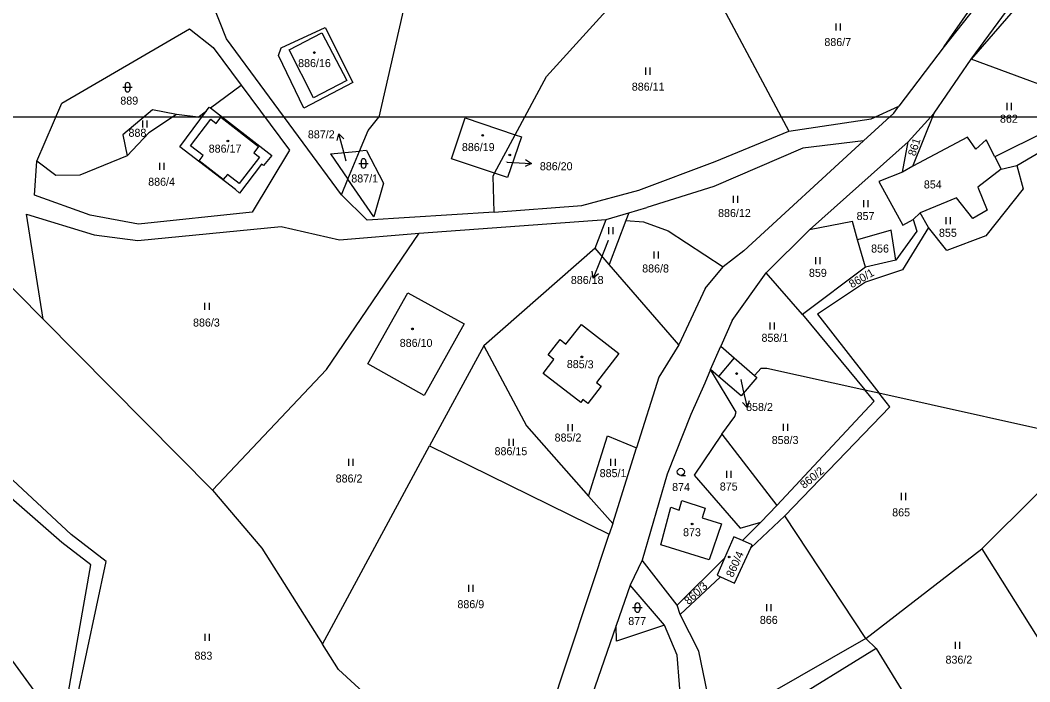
# Model space of a CAD drawing. Extents: x -670359 to -660124, y -978807 to -970072.
# Drawn here: x -669351.9 to -669137.4, y -977619.9 to -977479.4 of the extents above; entities that cross this region are included whole.
import ezdxf

# ---------------------------------------------------------------- set-up
doc = ezdxf.new("R2010")
doc.units = 0
for name, color, linetype in [('Hranice parcel', 7, 'Continuous'), ('ML1000', 7, 'Continuous'), ('Parcelní čísla', 7, 'Continuous'), ('Vnitřní kresba', 7, 'Continuous'), ('Značky budov', 7, 'Continuous'), ('Značky kultur', 7, 'Continuous')]:
    doc.layers.add(name, color=color, linetype=linetype)

msp = doc.modelspace()

# ---------------------------------------------------------------- linework, layer by layer
at = {"layer": 'Hranice parcel'}
for p, q in [((-669296.47, -977485.29), (-669287.14, -977480.93)), ((-669287.14, -977480.93), (-669281.27, -977492.61)), ((-669297.06, -977486.92), (-669296.47, -977485.29)), ((-669291.64, -977498.08), (-669297.06, -977486.92)), ((-669281.27, -977492.61), (-669291.64, -977498.08))]:
    msp.add_line(p, q, dxfattribs=at)
for points in [[(-669108.16, -977439.61), (-669149.88, -977487.66)], [(-669262.21, -977440.81), (-669275.7, -977499.98)], [(-669308.09, -977483.36), (-669317, -977460.78)], [(-669240.07, -977491.32), (-669212, -977460.35)], [(-669155.63, -977485.01), (-669142.12, -977465.6)], [(-669149.88, -977487.66), (-669133.84, -977465.83)], [(-669207.54, -977467.5), (-669188.62, -977502.97)], [(-669141.64, -977467.28), (-669155.63, -977485.01)], [(-669343.06, -977497.02), (-669315.95, -977481.19)], [(-669315.95, -977481.19), (-669310.92, -977485.22)], [(-669310.92, -977485.22), (-669305, -977493.18)], [(-669283.67, -977516.5), (-669308.09, -977483.36)], [(-669155.63, -977485.01), (-669165.21, -977497.66)], [(-669157.76, -977499.16), (-669149.88, -977487.66)], [(-669123.01, -977497.58), (-669149.88, -977487.66)], [(-669246.73, -977503.74), (-669240.07, -977491.32)], [(-669311.5, -977498.03), (-669305, -977493.18)], [(-669305, -977493.18), (-669294.73, -977507.01)], [(-669348.43, -977509.36), (-669343.06, -977497.02)], [(-669312.36, -977498.67), (-669311.75, -977497.84)], [(-669311.75, -977497.84), (-669311.5, -977498.03)], [(-669311.5, -977498.03), (-669298.5, -977508.1)], [(-669171.1, -977500.35), (-669165.21, -977497.66)], [(-669166.33, -977499.14), (-669165.21, -977497.66)], [(-669123.01, -977497.58), (-669144.82, -977508.4)], [(-669323.85, -977498.42), (-669330.14, -977503.73)], [(-669318.73, -977499.43), (-669324.63, -977503.3)], [(-669318.73, -977499.43), (-669323.85, -977498.42)], [(-669314.09, -977499.96), (-669318.73, -977499.43)], [(-669317.98, -977506.3), (-669312.36, -977498.67)], [(-669314.09, -977499.96), (-669312.36, -977498.67)], [(-669278.01, -977502.82), (-669275.7, -977499.98)], [(-669251.12, -977511.91), (-669260.28, -977508.84), (-669257.36, -977500.15)], [(-669257.36, -977500.15), (-669246.73, -977503.74)], [(-669166.33, -977499.14), (-669172.75, -977505.05)], [(-669163.23, -977505.23), (-669157.76, -977499.16)], [(-669162.29, -977510.43), (-669157.76, -977499.16)], [(-669140.19, -977510.25), (-669123.02, -977500.22)], [(-669188.62, -977502.97), (-669171.1, -977500.35)], [(-669330.14, -977503.73), (-669329.24, -977508.2)], [(-669324.63, -977503.3), (-669329.24, -977508.2)], [(-669279.84, -977507.23), (-669278.01, -977502.82)], [(-669251.12, -977511.91), (-669246.73, -977503.74)], [(-669246.73, -977503.74), (-669245.43, -977504.18), (-669248.36, -977512.84), (-669251.12, -977511.91)], [(-669204.3, -977509.42), (-669188.62, -977502.97)], [(-669150.65, -977504.22), (-669162.29, -977510.43)], [(-669148.9, -977506.79), (-669150.65, -977504.22)], [(-669306.22, -977515.38), (-669317.98, -977506.3)], [(-669185.65, -977506.58), (-669204.54, -977514.75)], [(-669198.14, -977528.41), (-669172.75, -977505.05)], [(-669172.75, -977505.05), (-669185.65, -977506.58)], [(-669184.19, -977523.89), (-669163.23, -977505.23)], [(-669164.45, -977511.7), (-669163.23, -977505.23)], [(-669146.65, -977504.79), (-669148.9, -977506.79)], [(-669144.82, -977508.4), (-669146.65, -977504.79)], [(-669329.24, -977508.2), (-669339.29, -977512.34)], [(-669294.73, -977507.01), (-669302.62, -977520.16)], [(-669298.5, -977508.1), (-669300.25, -977510.28)], [(-669285.98, -977507.78), (-669279.84, -977507.23)], [(-669285.98, -977507.78), (-669282.29, -977513.15)], [(-669282.29, -977513.15), (-669279.84, -977507.23)], [(-669278.38, -977507.1), (-669279.84, -977507.23)], [(-669278.38, -977507.1), (-669274.75, -977514.03)], [(-669144.82, -977508.4), (-669143.47, -977511.04)], [(-669348.91, -977516.54), (-669348.43, -977509.36)], [(-669344.33, -977512.37), (-669348.43, -977509.36)], [(-669300.64, -977509.97), (-669305.35, -977516.1)], [(-669300.25, -977510.28), (-669300.64, -977509.97)], [(-669220.45, -977515.51), (-669204.3, -977509.42)], [(-669162.29, -977510.43), (-669164.45, -977511.7)], [(-669143.47, -977511.04), (-669148.45, -977514.87)], [(-669143.47, -977511.04), (-669140.19, -977510.25)], [(-669140.19, -977510.25), (-669138.84, -977515.22)], [(-669339.29, -977512.34), (-669344.33, -977512.37)], [(-669283.67, -977516.5), (-669282.29, -977513.15)], [(-669276.79, -977521.15), (-669282.29, -977513.15)], [(-669251.43, -977512.49), (-669251.12, -977511.91)], [(-669251.24, -977520.17), (-669251.43, -977512.49)], [(-669164.45, -977511.7), (-669169.5, -977513.69)], [(-669274.75, -977514.03), (-669276.79, -977521.15)], [(-669204.54, -977514.75), (-669218.8, -977519.2)], [(-669169.5, -977513.69), (-669164.41, -977522.91)], [(-669148.45, -977514.87), (-669146.46, -977519.76)], [(-669138.84, -977515.22), (-669146.72, -977525.19)], [(-669337.08, -977520.79), (-669348.91, -977516.54)], [(-669305.35, -977516.1), (-669306.22, -977515.38)], [(-669278.22, -977521.9), (-669283.67, -977516.5)], [(-669232.6, -977518.73), (-669220.45, -977515.51)], [(-669153.02, -977517.1), (-669160.72, -977520.28)], [(-669149.51, -977521.51), (-669153.02, -977517.1)], [(-669251.24, -977520.17), (-669232.6, -977518.73)], [(-669222.6, -977520.3), (-669218.8, -977519.2)], [(-669347.06, -977542.92), (-669350.57, -977520.6)], [(-669350.57, -977520.6), (-669336.25, -977524.95)], [(-669326.83, -977522.73), (-669337.08, -977520.79)], [(-669302.62, -977520.16), (-669326.83, -977522.73)], [(-669251.24, -977520.17), (-669278.22, -977521.9)], [(-669267.17, -977524.66), (-669227.45, -977521.71)], [(-669229.76, -977527.85), (-669227.45, -977521.71)], [(-669227.45, -977521.71), (-669222.6, -977520.3)], [(-669222.6, -977520.3), (-669223.23, -977521.96)], [(-669164.41, -977522.91), (-669162.16, -977521.71)], [(-669160.72, -977520.28), (-669162.16, -977521.71)], [(-669162.16, -977521.71), (-669161.45, -977524.19)], [(-669158.97, -977523.4), (-669160.72, -977520.28)], [(-669146.46, -977519.76), (-669149.51, -977521.51)], [(-669326.97, -977526.2), (-669296.46, -977523.22)], [(-669296.46, -977523.22), (-669284.09, -977526.07)], [(-669223.23, -977521.96), (-669226.76, -977531.31)], [(-669223.23, -977521.96), (-669219.49, -977522.19)], [(-669219.49, -977522.19), (-669214.23, -977524.13)], [(-669193.43, -977533.07), (-669184.19, -977523.89)], [(-669175.05, -977522.16), (-669184.19, -977523.89)], [(-669174.03, -977526.08), (-669175.05, -977522.16)], [(-669158.97, -977523.4), (-669164.44, -977532.43)], [(-669155.06, -977528.29), (-669158.97, -977523.4)], [(-669336.25, -977524.95), (-669326.97, -977526.2)], [(-669286.84, -977553.62), (-669267.17, -977524.66)], [(-669284.09, -977526.07), (-669267.17, -977524.66)], [(-669214.23, -977524.13), (-669202.58, -977531.77)], [(-669166.89, -977524.02), (-669174.03, -977526.08)], [(-669165.87, -977530.34), (-669166.89, -977524.02)], [(-669161.45, -977524.19), (-669165.87, -977530.34)], [(-669146.72, -977525.19), (-669155.06, -977528.29)], [(-669363.13, -977526.7), (-669347.06, -977542.92)], [(-669229.76, -977527.85), (-669253.45, -977548.58)], [(-669226.76, -977531.31), (-669229.76, -977527.85)], [(-669172.29, -977531.84), (-669174.03, -977526.08)], [(-669198.14, -977528.41), (-669202.58, -977531.77)], [(-669165.87, -977530.34), (-669172.29, -977531.84)], [(-669211.97, -977548.38), (-669226.76, -977531.31)], [(-669206.41, -977536.39), (-669202.58, -977531.77)], [(-669172.29, -977531.84), (-669185.69, -977541.89)], [(-669164.44, -977532.43), (-669172.3, -977535.05)], [(-669200.67, -977543.21), (-669193.43, -977533.07)], [(-669185.69, -977541.89), (-669193.43, -977533.07)], [(-669206.41, -977536.39), (-669211.97, -977548.38)], [(-669172.3, -977535.05), (-669182.49, -977541.82)], [(-669278.06, -977552.4), (-669269.59, -977537.3)], [(-669269.59, -977537.3), (-669257.59, -977543.88)], [(-669311.1, -977579.22), (-669347.06, -977542.92)], [(-669200.67, -977543.21), (-669203.09, -977548.67)], [(-669185.69, -977541.89), (-669172.45, -977557.92)], [(-669182.49, -977541.82), (-669169.48, -977558.58)], [(-669257.59, -977543.88), (-669266.13, -977559.09)], [(-669236.01, -977548.19), (-669232.68, -977544.03)], [(-669232.68, -977544.03), (-669224.77, -977550.2)], [(-669239.77, -977550.48), (-669237.18, -977547.25)], [(-669237.18, -977547.25), (-669236.01, -977548.19)], [(-669253.45, -977548.58), (-669264.94, -977569.83)], [(-669253.45, -977548.58), (-669244.38, -977565.57)], [(-669211.97, -977548.38), (-669216.24, -977555.25)], [(-669205.27, -977553.6), (-669203.09, -977548.67)], [(-669203.09, -977548.67), (-669200.23, -977551.14)], [(-669240.79, -977554.44), (-669238.57, -977551.46)], [(-669238.57, -977551.46), (-669239.77, -977550.48)], [(-669224.77, -977550.2), (-669229.47, -977556.38)], [(-669200.23, -977551.14), (-669195.88, -977554.9)], [(-669311.1, -977579.22), (-669286.84, -977553.62)], [(-669266.13, -977559.09), (-669278.06, -977552.4)], [(-669205.27, -977553.6), (-669206.44, -977556.51)], [(-669199.77, -977562.65), (-669205.27, -977553.6)], [(-669203.55, -977555.07), (-669205.27, -977553.6)], [(-669195.88, -977554.9), (-669194.52, -977553.32)], [(-669194.52, -977553.32), (-669193.32, -977553.28)], [(-669193.32, -977553.28), (-669172.45, -977557.92)], [(-669232.83, -977560.61), (-669240.79, -977554.44)], [(-669216.24, -977555.25), (-669220.95, -977570.21)], [(-669198.76, -977559.21), (-669203.55, -977555.07)], [(-669195.4, -977555.31), (-669198.76, -977559.21)], [(-669195.88, -977554.9), (-669195.4, -977555.31)], [(-669228.49, -977557.16), (-669231.31, -977560.8)], [(-669229.47, -977556.38), (-669228.49, -977557.16)], [(-669206.44, -977556.51), (-669209.46, -977563.18)], [(-669170.46, -977560.33), (-669172.45, -977557.92)], [(-669172.45, -977557.92), (-669169.48, -977558.58)], [(-669232.36, -977559.99), (-669232.83, -977560.61)], [(-669231.31, -977560.8), (-669232.36, -977559.99)], [(-669191.19, -977582.52), (-669170.46, -977560.33)], [(-669167.18, -977561.54), (-669169.48, -977558.58)], [(-669169.48, -977558.58), (-669124.36, -977568.61)], [(-669167.18, -977561.54), (-669189.44, -977584.68)], [(-669341.12, -977588.67), (-669368.05, -977563.65)], [(-669209.46, -977563.18), (-669214.43, -977575.81)], [(-669202.83, -977567.36), (-669200.09, -977563.61)], [(-669200.09, -977563.61), (-669199.77, -977562.65)], [(-669343.11, -977590.36), (-669370.27, -977566.62)], [(-669244.38, -977565.57), (-669231.17, -977580.52)], [(-669231.17, -977580.52), (-669227.16, -977567.67)], [(-669227.16, -977567.67), (-669220.95, -977570.21)], [(-669202.83, -977567.36), (-669208.7, -977576.07)], [(-669202.83, -977567.36), (-669191.19, -977582.52)], [(-669147.59, -977591.68), (-669124.36, -977568.61)], [(-669287.69, -977611.91), (-669264.94, -977569.83)], [(-669264.94, -977569.83), (-669226.78, -977588.58)], [(-669226.03, -977586.34), (-669220.95, -977570.21)], [(-669214.43, -977575.81), (-669219.81, -977594.12)], [(-669208.7, -977576.07), (-669198.97, -977587.3)], [(-669311.1, -977579.22), (-669300.56, -977591.54)], [(-669226.03, -977586.34), (-669231.17, -977580.52)], [(-669211.93, -977583.5), (-669211.36, -977581.42)], [(-669211.36, -977581.42), (-669206.41, -977583.04)], [(-669215.8, -977590.85), (-669213.69, -977582.85)], [(-669213.69, -977582.85), (-669211.93, -977583.5)], [(-669206.41, -977583.04), (-669207.05, -977585.11)], [(-669194.57, -977586.03), (-669191.19, -977582.52)], [(-669207.05, -977585.11), (-669202.89, -977586.41)], [(-669198.97, -977587.3), (-669194.57, -977586.03)], [(-669194.57, -977586.03), (-669198.48, -977589.92)], [(-669189.44, -977584.68), (-669196.67, -977591.5)], [(-669172.23, -977610.73), (-669189.44, -977584.68)], [(-669226.03, -977586.34), (-669226.78, -977588.58)], [(-669202.89, -977586.41), (-669205.56, -977594)], [(-669336.93, -977595.11), (-669343.11, -977590.36)], [(-669333.65, -977594.37), (-669341.12, -977588.67)], [(-669239.62, -977627.27), (-669226.78, -977588.58)], [(-669200.29, -977589.11), (-669202.28, -977593.69)], [(-669198.48, -977589.92), (-669200.29, -977589.11)], [(-669196.37, -977590.86), (-669198.48, -977589.92)], [(-669300.56, -977591.54), (-669287.69, -977611.91)], [(-669205.56, -977594), (-669215.8, -977590.85)], [(-669200.17, -977599.01), (-669196.67, -977591.5)], [(-669196.67, -977591.5), (-669196.37, -977590.86)], [(-669172.23, -977610.73), (-669147.59, -977591.68)], [(-669147.59, -977591.68), (-669130.3, -977619.14)], [(-669339.81, -977623.26), (-669333.65, -977594.37)], [(-669219.81, -977594.12), (-669222.31, -977599.39)], [(-669212.32, -977603.66), (-669219.81, -977594.12)], [(-669202.28, -977593.69), (-669212.32, -977603.66)], [(-669202.28, -977593.69), (-669203.85, -977597.29)], [(-669347.25, -977624.1), (-669368.28, -977595.3)], [(-669341.89, -977623.27), (-669336.93, -977595.11)], [(-669203.16, -977597.61), (-669211.69, -977605.66)], [(-669203.85, -977597.29), (-669203.16, -977597.61)], [(-669203.16, -977597.61), (-669200.17, -977599.01)], [(-669222.31, -977599.39), (-669225.3, -977607.95)], [(-669215.06, -977607.89), (-669222.31, -977599.39)], [(-669211.69, -977605.66), (-669212.32, -977603.66)], [(-669207.71, -977613.43), (-669211.69, -977605.66)], [(-669225.3, -977607.95), (-669231.13, -977624.73)], [(-669225.24, -977611.31), (-669225.3, -977607.95)], [(-669215.06, -977607.89), (-669225.24, -977611.31)], [(-669212.35, -977614.3), (-669215.06, -977607.89)], [(-669172.23, -977610.73), (-669193.64, -977623)], [(-669172.23, -977610.73), (-669170.07, -977612.9)], [(-669284.27, -977617.33), (-669287.69, -977611.91)], [(-669204.48, -977629.2), (-669207.71, -977613.43)], [(-669170.07, -977612.9), (-669190.21, -977625.32)], [(-669170.07, -977612.9), (-669156.04, -977635.66)], [(-669210.82, -977632.95), (-669212.35, -977614.3)], [(-669284.27, -977617.33), (-669272.21, -977628.45)]]:
    msp.add_lwpolyline(points, dxfattribs=at)
at = {"layer": 'ML1000'}
msp.add_lwpolyline([(-668750, -977000), (-668750, -977500), (-669375, -977500), (-669375, -977000)], close=True, dxfattribs=at)
at = {"layer": 'Parcelní čísla'}
for p, q in [((-669284.59, -977504.97), (-669284.2, -977503.52)), ((-669282.68, -977509.3), (-669283.18, -977507.39)), ((-669248.54, -977509.57), (-669247.29, -977509.63)), ((-669244.56, -977509), (-669243.29, -977509.8)), ((-669227.01, -977526.16), (-669228.73, -977530.48)), ((-669229.03, -977533.27), (-669230.2, -977534.2)), ((-669198.83, -977555.7), (-669198.36, -977557.78)), ((-669197.03, -977560.25), (-669197.47, -977561.68))]:
    msp.add_line(p, q, dxfattribs=at)
for points in [[(-669283.18, -977507.39), (-669284.2, -977503.52), (-669283.14, -977504.59)], [(-669247.29, -977509.63), (-669243.29, -977509.8), (-669244.62, -977510.5)], [(-669228.73, -977530.48), (-669230.2, -977534.2), (-669230.42, -977532.71)], [(-669198.36, -977557.78), (-669197.47, -977561.68), (-669198.49, -977560.58)]]:
    msp.add_lwpolyline(points, dxfattribs=at)
at = {"layer": 'Vnitřní kresba'}
for p, q in [((-669294.77, -977485.67), (-669287.81, -977482.08)), ((-669287.81, -977482.08), (-669282.5, -977492.21)), ((-669289.59, -977495.88), (-669294.77, -977485.67)), ((-669282.5, -977492.21), (-669289.59, -977495.88))]:
    msp.add_line(p, q, dxfattribs=at)
for points in [[(-669310.3, -977501.32), (-669309.3, -977500.02)], [(-669309.3, -977500.02), (-669301.3, -977506.22)], [(-669315.78, -977506.05), (-669311.46, -977500.43)], [(-669311.46, -977500.43), (-669310.3, -977501.32)], [(-669313.04, -977508.15), (-669315.78, -977506.05)], [(-669301.3, -977506.22), (-669302.3, -977507.56)], [(-669313.88, -977509.25), (-669313.04, -977508.15)], [(-669301.08, -977508.47), (-669305.42, -977514.09)], [(-669302.3, -977507.56), (-669301.08, -977508.47)], [(-669308.78, -977513.26), (-669313.88, -977509.25)], [(-669307.92, -977512.15), (-669308.78, -977513.26)], [(-669305.42, -977514.09), (-669307.92, -977512.15)], [(-669200.23, -977551.14), (-669203.55, -977555.07)]]:
    msp.add_lwpolyline(points, dxfattribs=at)
at = {"layer": 'Značky budov'}
for centre in [(-669289.43, -977486.26), (-669253.66, -977503.86), (-669307.8, -977505.04), (-669268.59, -977544.97), (-669232.58, -977550.91), (-669199.71, -977554.46), (-669209.16, -977586.41), (-669201.29, -977593.42)]:
    msp.add_circle(centre, 0.175, dxfattribs=at)
at = {"layer": 'Značky kultur'}
for p, q in [((-669178.62, -977480.06), (-669178.62, -977481.56)), ((-669177.62, -977481.56), (-669177.62, -977480.06)), ((-669219.1, -977489.46), (-669219.1, -977490.96)), ((-669218.1, -977490.96), (-669218.1, -977489.46)), ((-669330.11, -977493.63), (-669328.11, -977493.63)), ((-669329.61, -977493.13), (-669329.61, -977494.13)), ((-669328.61, -977493.13), (-669328.61, -977494.13)), ((-669142.32, -977496.97), (-669142.32, -977498.47)), ((-669141.32, -977498.47), (-669141.32, -977496.97)), ((-669325.93, -977500.67), (-669325.93, -977502.17)), ((-669324.93, -977502.17), (-669324.93, -977500.67)), ((-669322.35, -977509.67), (-669322.35, -977511.17)), ((-669321.35, -977511.17), (-669321.35, -977509.67)), ((-669279.97, -977509.82), (-669277.97, -977509.82)), ((-669279.47, -977509.32), (-669279.47, -977510.32)), ((-669278.47, -977509.32), (-669278.47, -977510.32)), ((-669200.43, -977516.69), (-669200.43, -977518.19)), ((-669199.43, -977518.19), (-669199.43, -977516.69)), ((-669172.78, -977517.63), (-669172.78, -977519.13)), ((-669171.78, -977519.13), (-669171.78, -977517.63)), ((-669155.28, -977521.2), (-669155.28, -977522.7)), ((-669154.28, -977522.7), (-669154.28, -977521.2)), ((-669226.94, -977523.37), (-669226.94, -977524.87)), ((-669225.94, -977524.87), (-669225.94, -977523.37)), ((-669217.32, -977528.52), (-669217.32, -977530.02)), ((-669216.32, -977530.02), (-669216.32, -977528.52)), ((-669182.95, -977529.71), (-669182.95, -977531.21)), ((-669181.95, -977531.21), (-669181.95, -977529.71)), ((-669312.74, -977539.45), (-669312.74, -977540.95)), ((-669311.74, -977540.95), (-669311.74, -977539.45)), ((-669192.65, -977543.63), (-669192.65, -977545.13)), ((-669191.65, -977545.13), (-669191.65, -977543.63)), ((-669235.56, -977565.18), (-669235.56, -977566.68)), ((-669234.56, -977566.68), (-669234.56, -977565.18)), ((-669189.85, -977565.13), (-669189.85, -977566.63)), ((-669188.85, -977566.63), (-669188.85, -977565.13)), ((-669248.13, -977568.29), (-669248.13, -977569.79)), ((-669247.13, -977569.79), (-669247.13, -977568.29)), ((-669282.15, -977572.59), (-669282.15, -977574.09)), ((-669281.15, -977574.09), (-669281.15, -977572.59)), ((-669226.47, -977572.57), (-669226.47, -977574.07)), ((-669225.47, -977574.07), (-669225.47, -977572.57)), ((-669201.85, -977575.1), (-669201.85, -977576.6)), ((-669200.85, -977576.6), (-669200.85, -977575.1)), ((-669211.56, -977576.09), (-669210.56, -977576.09)), ((-669164.75, -977579.83), (-669164.75, -977581.33)), ((-669163.75, -977581.33), (-669163.75, -977579.83)), ((-669256.69, -977599.32), (-669256.69, -977600.82)), ((-669255.69, -977600.82), (-669255.69, -977599.32)), ((-669221.8, -977604.18), (-669219.8, -977604.18)), ((-669221.3, -977603.68), (-669221.3, -977604.68)), ((-669220.3, -977603.68), (-669220.3, -977604.68)), ((-669193.38, -977603.44), (-669193.38, -977604.94)), ((-669192.38, -977604.94), (-669192.38, -977603.44)), ((-669312.68, -977609.73), (-669312.68, -977611.23)), ((-669311.68, -977611.23), (-669311.68, -977609.73)), ((-669153.27, -977611.46), (-669153.27, -977612.96)), ((-669152.27, -977612.96), (-669152.27, -977611.46))]:
    msp.add_line(p, q, dxfattribs=at)
for centre, radius in [((-669289.43, -977486.26), 0.175), ((-669253.66, -977503.86), 0.175), ((-669307.8, -977505.04), 0.175), ((-669247.9, -977508.02), 0.175), ((-669268.59, -977544.97), 0.175), ((-669232.58, -977550.91), 0.175), ((-669199.71, -977554.46), 0.175), ((-669211.56, -977575.34), 0.75), ((-669209.16, -977586.41), 0.175), ((-669201.29, -977593.42), 0.175)]:
    msp.add_circle(centre, radius, dxfattribs=at)
for centre, start, end in [((-669329.11, -977493.13), 0, 180), ((-669329.11, -977494.13), 180, 0), ((-669278.97, -977509.32), 0, 180), ((-669278.97, -977510.32), 180, 0), ((-669220.8, -977603.68), 0, 180), ((-669220.8, -977604.68), 180, 0)]:
    msp.add_arc(centre, 0.5, start, end, dxfattribs=at)

# ---------------------------------------------------------------- texts
at = {"layer": 'Parcelní čísla'}
for s, height, p in [('886/7', 1.7, (-669181.06, -977484.88)), ('886/16', 1.7, (-669292.88, -977489.35)), ('886/11', 1.7, (-669221.98, -977494.36)), ('889', 1.7, (-669330.66, -977497.32)), ('862', 1.7, (-669143.75, -977501.17)), ('888', 1.7, (-669328.92, -977504.16)), ('887/2', 1.7, (-669290.81, -977504.49)), ('886/17', 1.7, (-669311.88, -977507.52)), ('886/19', 1.7, (-669258.08, -977507.19)), ('887/2', 0.1, (-669282.68, -977509.3)), ('886/20', 0.1, (-669248.78, -977509.57)), ('886/20', 1.7, (-669241.52, -977511.26)), ('886/4', 1.7, (-669324.74, -977514.56)), ('887/1', 1.7, (-669281.58, -977513.86)), ('854', 1.7, (-669159.92, -977515.13)), ('886/12', 1.7, (-669203.65, -977521.2)), ('857', 1.7, (-669174.21, -977521.83)), ('855', 1.7, (-669156.71, -977525.4)), ('886/18', 0.1, (-669227.25, -977526.16)), ('856', 1.7, (-669171.13, -977528.75)), ('886/8', 1.7, (-669219.77, -977532.98)), ('859', 1.7, (-669184.34, -977533.91)), ('886/18', 1.7, (-669234.93, -977535.42)), ('886/3', 1.7, (-669315.21, -977544.47)), ('886/10', 1.7, (-669271.29, -977548.79)), ('858/1', 1.7, (-669194.42, -977547.71)), ('858/2', 0.1, (-669198.83, -977555.7)), ('858/2', 1.7, (-669197.69, -977562.4)), ('885/2', 1.7, (-669238.38, -977568.9)), ('858/3', 1.7, (-669192.25, -977569.42)), ('886/15', 1.7, (-669251.14, -977571.8)), ('885/1', 1.7, (-669228.81, -977576.46)), ('886/2', 1.7, (-669284.9, -977577.6)), ('874', 1.7, (-669213.41, -977579.41)), ('875', 1.7, (-669203.28, -977579.3)), ('865', 1.7, (-669166.65, -977584.8)), ('873', 1.7, (-669211.09, -977589.01)), ('886/9', 1.7, (-669259.03, -977604.3)), ('877', 1.7, (-669222.73, -977607.88)), ('866', 1.7, (-669194.77, -977607.64)), ('883', 1.7, (-669314.9, -977615.23)), ('836/2', 1.7, (-669155.32, -977616.08))]:
    msp.add_text(s, height=height, dxfattribs=at).set_placement(p)
for s, rotation, p in [('861', 72.1201, (-669161.75, -977508.38)), ('860/1', 30.0029, (-669175.23, -977536.36)), ('885/3', 359.1235, (-669235.8, -977553.27)), ('860/2', 39.0938, (-669185.36, -977579.02)), ('860/4', 65.5533, (-669200.5, -977597.89)), ('860/3', 42.9432, (-669209.9, -977603.67))]:
    msp.add_text(s, height=1.7, rotation=rotation, dxfattribs=at).set_placement(p)

doc.saveas('drawing.dxf')
